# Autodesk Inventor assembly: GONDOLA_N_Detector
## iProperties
Shininess: 64.0
Length Units: 11272
Angle Units: 11279
Time Units: 11290
Mass Units: 11286
Length Display Precision: 3
Angle Display Precision: 2
Compacted: True
Part Number: GONDOLA_N_Detector
Document SubType Name: Assembly
Created: 2004-12
Designer: John Blackburn
Manufacturer: Standard
Standards Organization: Custom
Density: 0.0
Volumn: 0.0
Area: 0.0
PropertySet Name: Model Information
Control State: 0
Master: False
Checked Out: False
Author: John Blackburn
